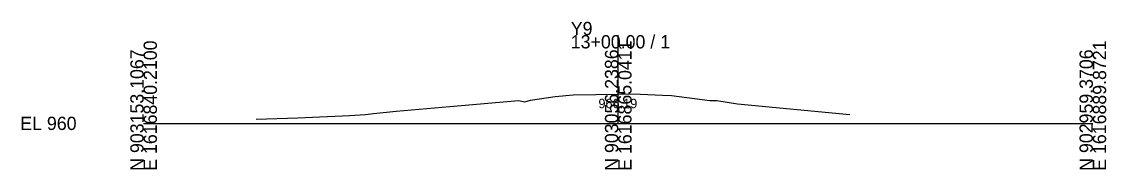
# Model space of a CAD drawing. Extents: x -26 to 1403, y -10 to 3021.
# Drawn here: x -25.7 to 202.8, y 2990.3 to 3021.5 of the extents above; entities that cross this region are included whole.
import ezdxf

# ---------------------------------------------------------------- set-up
doc = ezdxf.new("R2010")
doc.units = 0
for name, color, linetype in [('Exist Cross Section Cell', 7, 'Continuous'), ('Exist XS Center Line Elevation Label', 7, 'Continuous'), ('Exist XS Ground Line', 7, 'Continuous')]:
    doc.layers.add(name, color=color, linetype=linetype)

msp = doc.modelspace()

# ---------------------------------------------------------------- linework, layer by layer
at = {"layer": 'Exist Cross Section Cell'}
for p, q in [((100, 3000), (100, 3018.61)), ((0, 3000), (100, 3000)), ((100, 3000), (200, 3000))]:
    msp.add_line(p, q, dxfattribs=at)
at = {"layer": 'Exist XS Ground Line'}
for p, q in [((81.5, 3004.9), (86.69, 3005.64)), ((86.69, 3005.64), (90.48, 3006.05)), ((90.48, 3006.05), (95.27, 3006.09)), ((95.27, 3006.09), (100, 3006.19)), ((100, 3006.19), (100.66, 3006.2)), ((100.66, 3006.2), (104.71, 3006.13)), ((104.71, 3006.13), (109.35, 3005.97)), ((109.35, 3005.97), (111.25, 3005.85)), ((111.25, 3005.85), (119.27, 3004.84)), ((53.2, 3002.56), (64.55, 3003.58)), ((64.55, 3003.58), (78.97, 3004.85)), ((78.97, 3004.85), (80.33, 3004.52)), ((80.33, 3004.52), (81.5, 3004.9)), ((119.27, 3004.84), (120.77, 3004.81)), ((120.77, 3004.81), (125.13, 3004.15)), ((125.13, 3004.15), (148.77, 3001.9)), ((23.74, 3000.86), (32.46, 3001.18)), ((32.46, 3001.18), (43.37, 3001.63)), ((43.37, 3001.63), (46.76, 3001.89)), ((46.76, 3001.89), (48.41, 3002.08)), ((48.41, 3002.08), (53.2, 3002.56))]:
    msp.add_line(p, q, dxfattribs=at)

# ---------------------------------------------------------------- texts
at = {"layer": 'Exist Cross Section Cell'}
for s, p in [('Y9', (90, 3018.61)), ('13+00.00 / 1', (90, 3015.81)), ('EL 960', (-26, 2998.6))]:
    msp.add_text(s, height=2.8, dxfattribs=at).set_placement(p)
for s, p in [('E 1616840.2100', (2.8, 2990)), ('E 1616865.0411', (102.8, 2990)), ('E 1616889.8721', (202.8, 2990)), ('N 903153.1067', (0, 2990)), ('N 903056.2386', (100, 2990)), ('N 902959.3706', (200, 2990))]:
    msp.add_text(s, height=2.8, rotation=90, dxfattribs=at).set_placement(p)
at = {"layer": 'Exist XS Center Line Elevation Label'}
msp.add_text('966.19', height=2, dxfattribs=at).set_placement((95.83, 3003.19))

doc.saveas('drawing.dxf')
